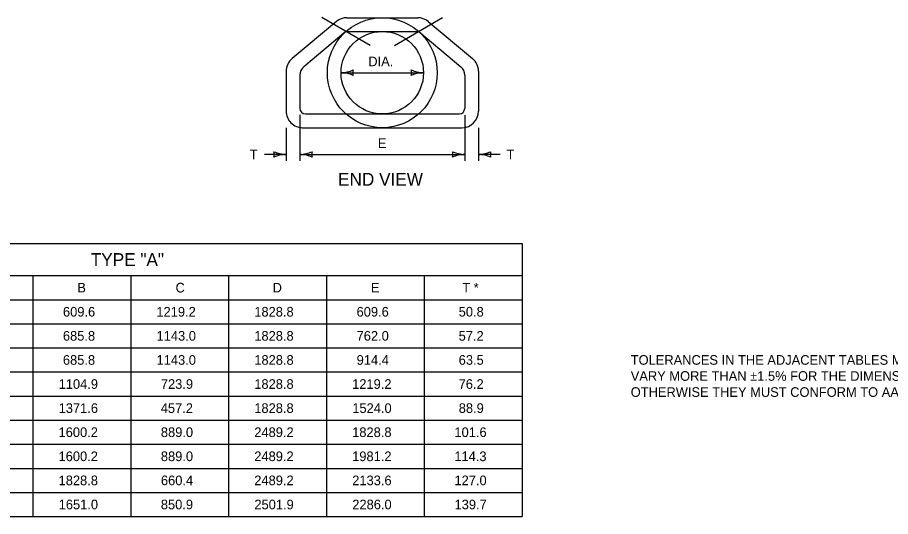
# Model space of a CAD drawing. Extents: x 49991.4 to 50022.1, y 49985 to 50011.4.
# Drawn here: x 50003.22 to 50008.67, y 49992.98 to 49996.08 of the extents above; entities that cross this region are included whole.
import ezdxf

# ---------------------------------------------------------------- set-up
doc = ezdxf.new("R2010")
doc.units = 0
for name, color, linetype in [('Level 1', 7, 'Continuous'), ('Level 2', 7, 'Continuous'), ('Level 3', 7, 'Continuous'), ('Level 4', 7, 'Continuous'), ('Level 5', 7, 'Continuous')]:
    doc.layers.add(name, color=color, linetype=linetype)

msp = doc.modelspace()

# ---------------------------------------------------------------- linework, layer by layer
at = {"layer": 'Level 1'}
for p, q in [((50005.2121, 49996.0591), (50004.9361, 49995.828)), ((50005.278, 49996.083), (50005.7191, 49996.083)), ((50005.7851, 49996.0591), (50006.0611, 49995.828)), ((50005.2717, 49995.9973), (50005.0093, 49995.7777)), ((50005.2723, 49995.9973), (50005.725, 49995.9973)), ((50005.7253, 49995.9973), (50005.9877, 49995.7777)), ((50004.8992, 49995.7492), (50004.8992, 49995.5009)), ((50004.9849, 49995.7252), (50004.9849, 49995.518)), ((50006.0122, 49995.7252), (50006.0122, 49995.518)), ((50006.0979, 49995.7492), (50006.0979, 49995.5009)), ((50005.0191, 49995.4837), (50005.978, 49995.4837)), ((50005, 49995.3981), (50005.9951, 49995.3981))]:
    msp.add_line(p, q, dxfattribs=at)
msp.add_circle((50005.4986, 49995.7405), 0.2568, dxfattribs=at)
for centre, radius, start, end in [((50005.278, 49995.9803), 0.1027, 90, 129.9017), ((50005.7191, 49995.9803), 0.1027, 50.0941, 90), ((50005.002, 49995.7492), 0.1027, 129.9211, 180), ((50005.9951, 49995.7493), 0.1027, 0, 50.0781), ((50005.0534, 49995.7252), 0.0685, 129.9484, 180), ((50005.9438, 49995.7252), 0.0685, 0, 50.0789), ((50005.002, 49995.5009), 0.1028, 179.994, 269.994), ((50005.0192, 49995.518), 0.0343, 179.9164, 269.9164), ((50005.978, 49995.5179), 0.0342, 270, 0), ((50005.9951, 49995.5008), 0.1027, 270, 0)]:
    msp.add_arc(centre, radius, start, end, dxfattribs=at)
at = {"layer": 'Level 2'}
for p, q in [((50001.4902, 49994.677), (50006.3702, 49994.677)), ((50006.3702, 49994.677), (50006.3702, 49992.977)), ((50006.3702, 49994.677), (50006.3702, 49992.977)), ((50001.4902, 49994.477), (50006.3702, 49994.477)), ((50003.3202, 49994.477), (50003.3202, 49992.977)), ((50003.9302, 49994.477), (50003.9302, 49992.977)), ((50004.5402, 49994.477), (50004.5402, 49992.977)), ((50005.1502, 49994.477), (50005.1502, 49992.977)), ((50005.7602, 49994.477), (50005.7602, 49992.977)), ((50001.4902, 49994.327), (50006.3702, 49994.327)), ((50001.4902, 49994.177), (50006.3702, 49994.177)), ((50001.4902, 49994.027), (50006.3702, 49994.027)), ((50001.4902, 49993.877), (50006.3702, 49993.877)), ((50001.4902, 49993.727), (50006.3702, 49993.727)), ((50001.4902, 49993.577), (50006.3702, 49993.577)), ((50001.4902, 49993.427), (50006.3702, 49993.427)), ((50001.4902, 49993.277), (50006.3702, 49993.277)), ((50001.4902, 49993.127), (50006.3702, 49993.127)), ((50001.4902, 49992.977), (50006.3702, 49992.977))]:
    msp.add_line(p, q, dxfattribs=at)
at = {"layer": 'Level 3'}
for p, q in [((50005.2417, 49995.7406), (50005.7554, 49995.7406)), ((50004.9849, 49995.4779), (50004.9849, 49995.1915)), ((50006.0122, 49995.4757), (50006.0122, 49995.1915)), ((50004.8992, 49995.3981), (50004.8992, 49995.1915)), ((50006.0979, 49995.3981), (50006.0979, 49995.1915)), ((50004.8992, 49995.2315), (50004.7643, 49995.2315)), ((50004.9849, 49995.2315), (50006.0122, 49995.2315)), ((50006.2328, 49995.2315), (50006.0979, 49995.2315))]:
    msp.add_line(p, q, dxfattribs=at)
for centre, radius, start, end in [((50005.2302, 49995.9733), 0.233, 272.8273, 292.0772), ((50005.2326, 49995.5185), 0.2223, 67.456, 87.6395), ((50005.3699, 49995.7406), 0.0548, 162.1388, 197.8612), ((50005.7646, 49995.9627), 0.2223, 247.456, 267.6395), ((50005.6272, 49995.7406), 0.0548, 342.1388, 17.8612), ((50005.7669, 49995.5079), 0.233, 92.8273, 112.0772), ((50004.9084, 49995.4536), 0.2223, 247.456, 267.6395), ((50004.771, 49995.2315), 0.0548, 342.1388, 17.8612), ((50004.9107, 49994.9988), 0.233, 92.8273, 112.0772), ((50004.9734, 49995.4642), 0.233, 272.8273, 292.0772), ((50004.9757, 49995.0094), 0.2223, 67.456, 87.6395), ((50005.1131, 49995.2315), 0.0548, 162.1388, 197.8612), ((50006.0214, 49995.4536), 0.2223, 247.456, 267.6395), ((50005.884, 49995.2315), 0.0548, 342.1388, 17.8612), ((50006.0237, 49994.9988), 0.233, 92.8273, 112.0772), ((50006.0864, 49995.4642), 0.233, 272.8273, 292.0772), ((50006.0887, 49995.0094), 0.2223, 67.456, 87.6395), ((50006.2261, 49995.2315), 0.0548, 162.1388, 197.8612)]:
    msp.add_arc(centre, radius, start, end, dxfattribs=at)
at = {"layer": 'Level 4'}
msp.add_circle((50005.4986, 49995.7405), 0.3425, dxfattribs=at)
at = {"layer": 'Level 5'}
for p, q in [((50005.423, 49995.9103), (50005.1216, 49996.0844)), ((50005.575, 49995.9105), (50005.8746, 49996.0836))]:
    msp.add_line(p, q, dxfattribs=at)

# ---------------------------------------------------------------- texts
at = {"layer": 'Level 2'}
for s, height, p in [('DIA.', 0.06, (50005.4111, 49995.7806)), ('E', 0.06, (50005.4706, 49995.2715)), ('T', 0.06, (50004.6723, 49995.2015)), ('T', 0.06, (50006.2728, 49995.2015)), ('END VIEW', 0.08, (50005.2229, 49995.037)), ('TYPE "A"', 0.08, (50003.6814, 49994.537)), ('B', 0.06, (50003.5975, 49994.372)), ('C', 0.06, (50004.2097, 49994.372)), ('D', 0.06, (50004.8149, 49994.372)), ('E', 0.06, (50005.4272, 49994.372)), ('T *', 0.06, (50005.997, 49994.372)), ('609.6', 0.06, (50003.5081, 49994.222)), ('1219.2', 0.06, (50004.0905, 49994.222)), ('1828.8', 0.06, (50004.7006, 49994.222)), ('609.6', 0.06, (50005.3381, 49994.222)), ('50.8', 0.06, (50005.9746, 49994.222)), ('685.8', 0.06, (50003.5076, 49994.072)), ('1143.0', 0.06, (50004.0914, 49994.072)), ('1828.8', 0.06, (50004.7007, 49994.072)), ('762.0', 0.06, (50005.3383, 49994.072)), ('57.2', 0.06, (50005.9744, 49994.072)), ('685.8', 0.06, (50003.5076, 49993.922)), ('1143.0', 0.06, (50004.0914, 49993.922)), ('1828.8', 0.06, (50004.7007, 49993.922)), ('914.4', 0.06, (50005.3386, 49993.922)), ('63.5', 0.06, (50005.9746, 49993.922)), ('TOLERANCES IN THE ADJACENT TABLES MAY NOT', 0.06, (50007.047, 49993.922)), ('VARY MORE THAN ±1.5% FOR THE DIMENSIONS SHOWN.', 0.06, (50007.047, 49993.822)), ('1104.9', 0.06, (50003.4811, 49993.772)), ('723.9', 0.06, (50004.1181, 49993.772)), ('1828.8', 0.06, (50004.7006, 49993.772)), ('1219.2', 0.06, (50005.3105, 49993.772)), ('76.2', 0.06, (50005.9744, 49993.772)), ('OTHERWISE THEY MUST CONFORM TO AASHTO M 170.', 0.06, (50007.047, 49993.722)), ('1371.6', 0.06, (50003.4811, 49993.622)), ('457.2', 0.06, (50004.1174, 49993.622)), ('1828.8', 0.06, (50004.7006, 49993.622)), ('1524.0', 0.06, (50005.3114, 49993.622)), ('88.9', 0.06, (50005.975, 49993.622)), ('1600.2', 0.06, (50003.4805, 49993.472)), ('889.0', 0.06, (50004.1183, 49993.472)), ('2489.2', 0.06, (50004.7005, 49993.472)), ('1828.8', 0.06, (50005.3107, 49993.472)), ('101.6', 0.06, (50005.9481, 49993.472)), ('1600.2', 0.06, (50003.4805, 49993.322)), ('889.0', 0.06, (50004.1183, 49993.322)), ('2489.2', 0.06, (50004.7005, 49993.322)), ('1981.2', 0.06, (50005.3105, 49993.322)), ('114.3', 0.06, (50005.9474, 49993.322)), ('1828.8', 0.06, (50003.4807, 49993.172)), ('660.4', 0.06, (50004.1186, 49993.172)), ('2489.2', 0.06, (50004.7005, 49993.172)), ('2133.6', 0.06, (50005.3111, 49993.172)), ('127.0', 0.06, (50005.9483, 49993.172)), ('1651.0', 0.06, (50003.4814, 49993.022)), ('850.9', 0.06, (50004.1181, 49993.022)), ('2501.9', 0.06, (50004.7011, 49993.022)), ('2286.0', 0.06, (50005.3114, 49993.022)), ('139.7', 0.06, (50005.9488, 49993.022))]:
    msp.add_text(s, height=height, dxfattribs=at).set_placement(p)

doc.saveas('drawing.dxf')
